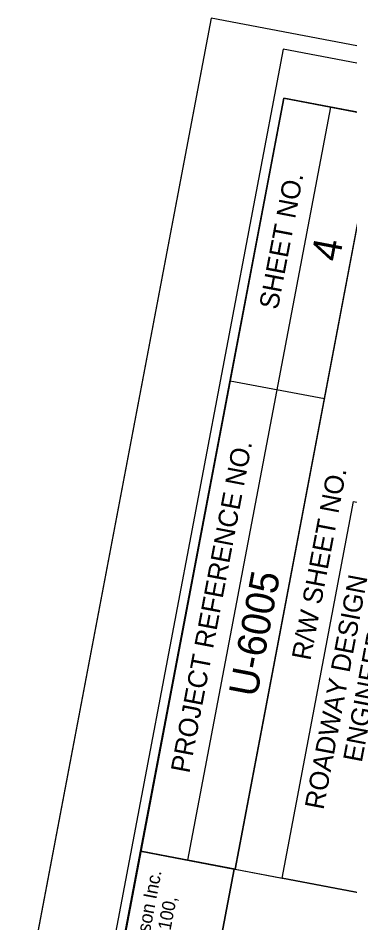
# Model space of a CAD drawing. Extents: x 1615685 to 1617075, y 899072 to 901363.
# Drawn here: x 1615949.1 to 1616035.7, y 900930.9 to 901167 of the extents above; entities that cross this region are included whole.
import ezdxf

# ---------------------------------------------------------------- set-up
doc = ezdxf.new("R2010")
doc.units = 0
for name, color, linetype in [('Default', 7, 'Continuous'), ('Exist Plan Preparation Drainage Flow Arrows', 7, 'Continuous'), ('Exist Plan Preparation Drainage Notes Label', 7, 'Continuous'), ('Exist Plan Preparation Watershed Blue', 7, 'Continuous'), ('Exist Structure Minor Pipes CMP 24 Inch Text', 7, 'Continuous'), ('Prop Drainage Structure Drop Inlet Grate 840 16 CELL', 7, 'Continuous'), ('Scratch_Level_7', 7, 'Continuous'), ('Scratch_Level_8', 7, 'Continuous')]:
    doc.layers.add(name, color=color, linetype=linetype)

msp = doc.modelspace()

# ---------------------------------------------------------------- linework, layer by layer
at = {"layer": 'Default'}
msp.add_lwpolyline([(1615979.8, 900809.83), (1616005.46, 900944.95), (1615981.08, 900949.57), (1615955.42, 900814.46)], close=True, dxfattribs=at)
at = {"layer": 'Exist Plan Preparation Drainage Flow Arrows'}
msp.add_lwpolyline([(1616744, 899325.3), (1617054.75, 900962.05), (1616018.28, 901158.86), (1615707.51, 899522.1)], close=True, dxfattribs=at)
at = {"layer": 'Exist Plan Preparation Drainage Notes Label'}
msp.add_lwpolyline([(1616761.22, 899308.8), (1617075.25, 900962.75), (1615999.47, 901167.01), (1615685.44, 899513.06)], close=True, dxfattribs=at)
at = {"layer": 'Exist Plan Preparation Watershed Blue'}
msp.add_lwpolyline([(1615955.42, 900814.46), (1615981.06, 900949.58), (1616005.46, 900944.95), (1615979.82, 900809.83)], close=True, dxfattribs=at)
at = {"layer": 'Exist Structure Minor Pipes CMP 24 Inch Text'}
msp.add_line((1615999.47, 901167.01), (1615685.44, 899513.06), dxfattribs=at)
at = {"layer": 'Prop Drainage Structure Drop Inlet Grate 840 16 CELL'}
msp.add_lwpolyline([(1616181.54, 900871.6), (1616226.17, 901106.67), (1616018.4, 901146.15), (1615973.76, 900911.05)], close=True, dxfattribs=at)
at = {"layer": 'Scratch_Level_8'}
for p, q in [((1615993.39, 900947.22), (1616030.72, 901143.76)), ((1616005.71, 900944.9), (1616043, 901141.43)), ((1616005.71, 900944.9), (1616043, 901141.43)), ((1616004.46, 901072.38), (1616029.03, 901067.77)), ((1616005.71, 900944.9), (1616017.98, 900942.57))]:
    msp.add_line(p, q, dxfattribs=at)
for points in [[(1616018.4, 901146.14), (1615738.59, 899672.43), (1616770.16, 899476.57), (1617049.96, 900950.25)], [(1615981.06, 900949.58), (1616018.4, 901146.14), (1616043, 901141.43), (1616005.71, 900944.9)], [(1616770.16, 899476.57), (1615738.61, 899672.4), (1615981.06, 900949.58), (1616128.49, 900921.6), (1616165.82, 901118.12), (1617049.96, 900950.25)], [(1616017.98, 900942.57), (1616036.64, 901040.86), (1616147.18, 901019.87), (1616128.49, 900921.6)]]:
    msp.add_lwpolyline(points, close=True, dxfattribs=at)

# ---------------------------------------------------------------- texts
at = {"layer": 'Default'}
for s, height, p in [('Johnson, Mirmiran, & Thompson Inc.', 3.5139, (1615972.23, 900868.92)), ('4700 Falls of Neuse Rd, Suite 100, ', 3.4135, (1615977.3, 900867.96))]:
    msp.add_text(s, height=height, rotation=79.2488, dxfattribs=at).set_placement(p)
at = {"layer": 'Scratch_Level_7'}
for s, p in [('4', (1616032.89, 901103.2)), ('U-6005', (1616011.38, 900989.56))]:
    msp.add_text(s, height=7.5, rotation=79.2494, dxfattribs=at).set_placement(p)
at = {"layer": 'Scratch_Level_8'}
for s, height, p in [('SHEET NO.', 5, (1616016.86, 901090.74)), ('PROJECT REFERENCE NO.', 5.0001, (1615993.78, 900969.76)), ('R/W SHEET NO.', 5.0001, (1616025.37, 900999.18)), ('ROADWAY DESIGN', 5.0001, (1616028.77, 900960.24)), ('ENGINEER', 5, (1616038.78, 900972.58))]:
    msp.add_text(s, height=height, rotation=79.2494, dxfattribs=at).set_placement(p)

doc.saveas('drawing.dxf')
